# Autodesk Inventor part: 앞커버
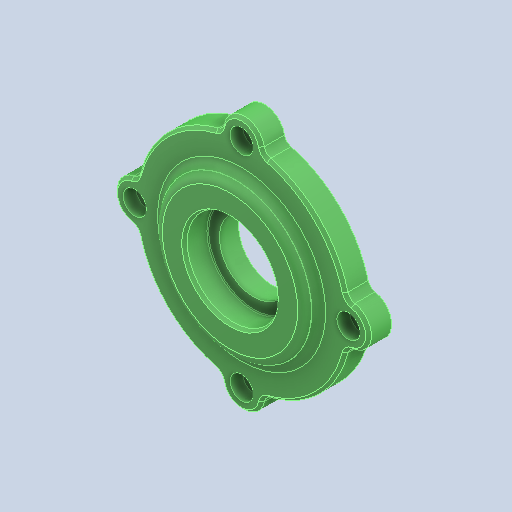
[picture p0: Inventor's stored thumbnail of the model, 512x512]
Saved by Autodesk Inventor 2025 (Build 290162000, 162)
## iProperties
Created: 2024-08
Part Number: 앞커버
Material: 알루미늄 6061
Document SubType Name: Modeling
Designer: hsj03
Density: 2.71 g/cm^3
Appearance: 기본값
Company: 한국ATC센터
Author: jhkim
Sending System: Autodesk Inventor 2025
Preprocessor: ST-DEVELOPER v20
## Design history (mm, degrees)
feature "솔리드1"
node "솔리드2"
